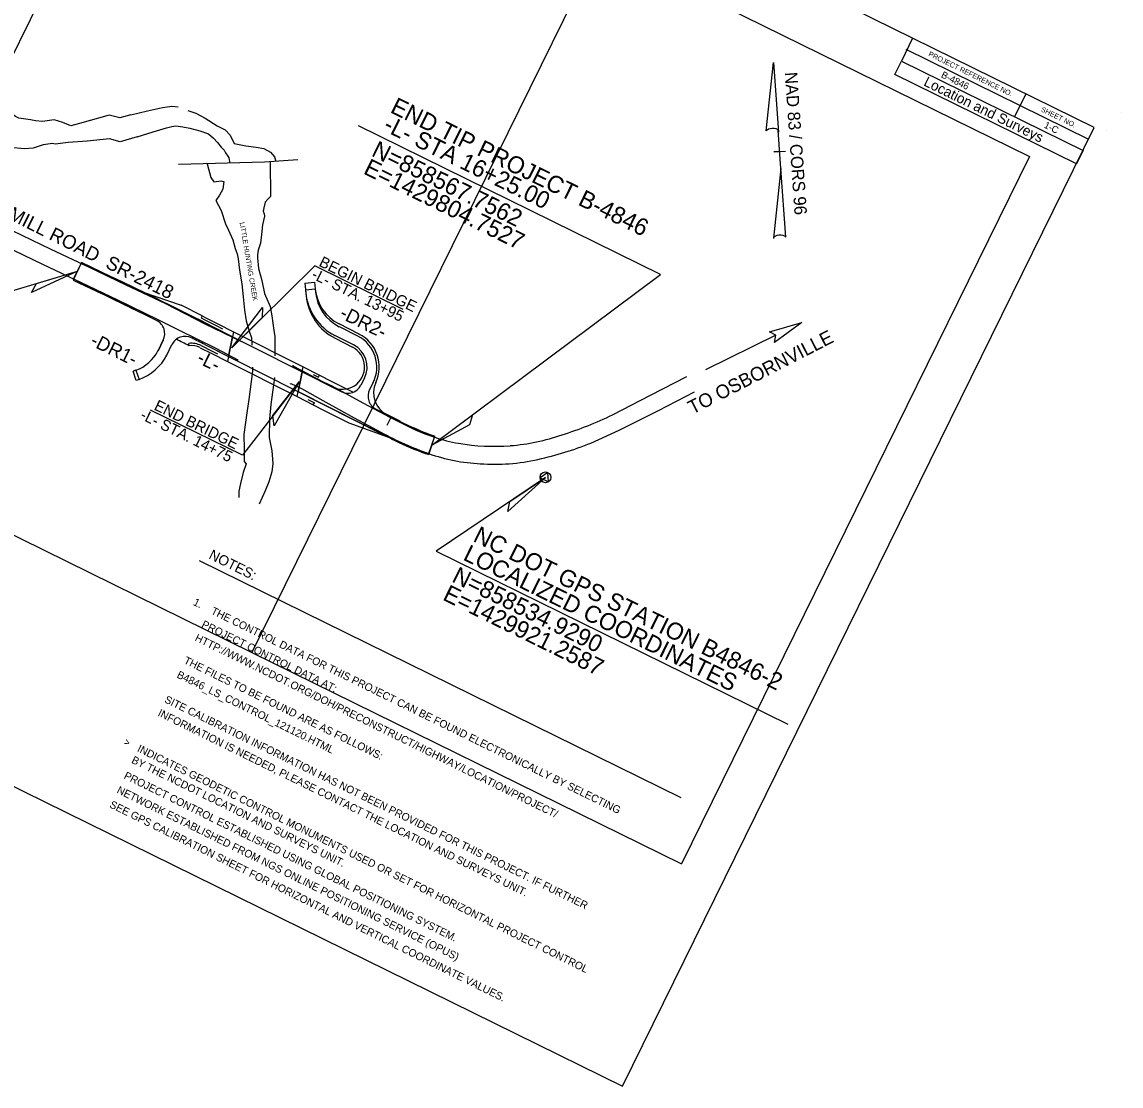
# Model space of a CAD drawing. Extents: x 1428428 to 1430511, y 857911 to 859585.
# Drawn here: x 1429385 to 1430511, y 857911 to 859002 of the extents above; entities that cross this region are included whole.
import ezdxf

# ---------------------------------------------------------------- set-up
doc = ezdxf.new("R2010")
doc.units = 0
for name, color, linetype in [('CTL NGS Horizontal CELL', 7, 'Continuous'), ('CTL Sheet Border CELL', 7, 'Continuous'), ('CTL Sheet Datum Description CELL', 7, 'Continuous'), ('CTL Sheet Notes CELL', 7, 'Continuous'), ('Default', 7, 'Continuous'), ('Exist Hydro Jurisdictional Stream or Body of Water', 7, 'Continuous'), ('Exist Other Culture Dam', 7, 'Continuous'), ('Exist Roads EOP', 7, 'Continuous'), ('Prop Conc Shoulder Berm Gutter', 7, 'Continuous'), ('Prop EOT', 7, 'Continuous'), ('Prop Paved Shoulder', 7, 'Continuous'), ('Prop Roadway Bridge', 7, 'Continuous'), ('Scratch_Level_0', 7, 'Continuous'), ('Scratch_Level_3', 7, 'Continuous'), ('Sheet Data Field CELL', 7, 'Continuous')]:
    doc.layers.add(name, color=color, linetype=linetype)

# ---------------------------------------------------------------- blocks, each defined once
blk = doc.blocks.new('CTL NGS HORIZONTAL')
at = {"layer": 'CTL NGS Horizontal CELL'}
blk.add_line((0, 0), (0, 0), dxfattribs=at)
blk.add_lwpolyline([(-0.064, -0.037), (0.064, -0.037), (0, 0.074), (-0.064, -0.037)], dxfattribs=at)
blk.add_circle((0, 0), 0.0738, dxfattribs=at)

msp = doc.modelspace()

# ---------------------------------------------------------------- linework, layer by layer
at = {"layer": 'CTL Sheet Border CELL'}
for p, q in [((1430297.8, 858985.3), (1430286.3, 858961.8)), ((1430291, 858974.1), (1430478.3, 858881.9)), ((1430413.8, 858928.2), (1430402.3, 858904.8)), ((1430511.5, 858909.2), (1430511.5, 858909.2)), ((1430496.9, 858890.3), (1430496.9, 858890.3)), ((1430496.9, 858890.3), (1430496.9, 858890.3))]:
    msp.add_line(p, q, dxfattribs=at)
for points in [[(1430484, 858893.6), (1429079.6, 859584.7), (1428595.9, 858601.6), (1430000.3, 857910.6)], [(1430286.3, 858961.8), (1430472.5, 858870.2), (1430465.7, 858856.4), (1430279.5, 858948.1)]]:
    msp.add_lwpolyline(points, close=True, dxfattribs=at)
at = {"layer": 'CTL Sheet Notes CELL'}
msp.add_line((1429566.2, 858449.5), (1430060, 858206.5), dxfattribs=at)
at = {"layer": 'Default'}
for p, q in [((1430147.7, 858890.2), (1430155.2, 858960.4)), ((1430155.3, 858960.5), (1430155.2, 858960.4)), ((1430155.3, 858960.5), (1430155.2, 858960.4)), ((1430155.3, 858960.5), (1430160.2, 858888.9)), ((1430162.8, 858851.8), (1430160.1, 858891)), ((1430160.2, 858888.9), (1430160.1, 858890.9)), ((1430155.6, 858868.8), (1430155.5, 858868.7)), ((1430160.9, 858869.1), (1430155.6, 858868.8)), ((1430155.7, 858868.8), (1430167.6, 858869.6)), ((1430162.8, 858851.8), (1430155.2, 858780.2)), ((1430167.7, 858781.4), (1430162.8, 858851.8)), ((1429246.2, 858687.6), (1429441.4, 858746.3)), ((1429599.6, 858667.9), (1429684.9, 858751.7)), ((1429775.5, 858707.1), (1429684.9, 858751.7)), ((1430157.5, 858680.6), (1430085.4, 858645.2)), ((1429668.7, 858633), (1429610.6, 858557.5)), ((1429610.6, 858557.5), (1429516.3, 858603.9))]:
    msp.add_line(p, q, dxfattribs=at)
for points in [[(1429804.7, 858567.8), (1430039.3, 858743.1), (1429729.5, 858895.5)], [(1429921.3, 858534.9), (1429809.1, 858459.2), (1430169.8, 858281.7)]]:
    msp.add_lwpolyline(points, dxfattribs=at)
for points in [[(1429441.4, 858746.3), (1429394.2, 858724.4), (1429399.3, 858733.6)], [(1429599.6, 858667.9), (1429631.1, 858709.2), (1429630.9, 858698.7)], [(1430151.2, 858684), (1430184.1, 858693.6), (1430156.3, 858673.3), (1430157.5, 858680.6)], [(1429668.7, 858633), (1429643.1, 858587.7), (1429641.9, 858598.2)], [(1429804.7, 858567.8), (1429846.4, 858598.9), (1429843.3, 858588.8)], [(1429921.3, 858534.9), (1429882.7, 858500), (1429884.9, 858510.3)]]:
    msp.add_lwpolyline(points, close=True, dxfattribs=at)
for centre, start_param, end_param in [((1430154, 858889.9), 0.216388, 2.908219), ((1430161.5, 858780.4), 0.201328, 3.141593)]:
    msp.add_ellipse(centre, major_axis=(6.33, 0.39), ratio=0.461098, start_param=start_param, end_param=end_param, dxfattribs=at)
at = {"layer": 'Exist Hydro Jurisdictional Stream or Body of Water'}
for points in [[(1429496.1, 858906.8), (1429485, 858903.6), (1429474, 858906.5), (1429443.7, 858898), (1429434.6, 858895.6), (1429426.5, 858899), (1429417.5, 858901.5), (1429405.7, 858899.9), (1429398.5, 858900.6), (1429393.3, 858901.7), (1429381.5, 858903.3), (1429378, 858905.2), (1429372.1, 858909.4), (1429367.1, 858910.6), (1429362.2, 858912.1), (1429362.2, 858912.2)], [(1429496.1, 858906.8), (1429513.2, 858910.8), (1429528.5, 858914.2), (1429538.4, 858915.5), (1429544.7, 858914.9)], [(1429554.8, 858911.3), (1429562.8, 858908.4), (1429572.3, 858903.4), (1429584.8, 858895.6), (1429592.9, 858891.2), (1429598.2, 858885.9), (1429602, 858877.5), (1429614.1, 858874.9), (1429624.8, 858873.5), (1429632.6, 858872.2), (1429639.5, 858868.3), (1429643.4, 858863.7), (1429644.7, 858859.1)], [(1429502.6, 858884.1), (1429485.3, 858879.1), (1429474.2, 858882), (1429451.4, 858879.7), (1429431.8, 858878.5), (1429418.7, 858876.6), (1429415.9, 858877.4), (1429406.2, 858876), (1429396.1, 858872.6), (1429387.1, 858871.9), (1429372.6, 858873.2), (1429361.1, 858876.6), (1429353.7, 858881.2), (1429349.9, 858886.1), (1429346.5, 858892.4), (1429345.9, 858893.4)], [(1429502.6, 858884.1), (1429519.2, 858889.3), (1429532.6, 858893.3), (1429538.2, 858894.8), (1429542.4, 858895.4), (1429549.4, 858894.5), (1429556.6, 858892.9), (1429566.9, 858890.4), (1429575.8, 858887.1), (1429580.8, 858882.7), (1429584.9, 858878.4), (1429588.8, 858873.5), (1429592, 858870.4), (1429592.4, 858869.8), (1429593.4, 858867.6), (1429595.8, 858864.4), (1429596.6, 858862.5), (1429597.6, 858857.2)], [(1429574.5, 858856.6), (1429578.3, 858842.4), (1429581.4, 858838.1), (1429588.9, 858838.9), (1429591.7, 858838.2), (1429590.6, 858830.4), (1429587.1, 858824.3), (1429583.5, 858818.8), (1429588.7, 858808.5), (1429593.3, 858795.1), (1429596.4, 858788.5), (1429600.9, 858778.7), (1429603.1, 858769.6), (1429605.2, 858764.2), (1429606.2, 858759.2), (1429607.7, 858747.4), (1429610.1, 858733.3), (1429611.4, 858719.9), (1429612.8, 858706.5), (1429614.4, 858695.4), (1429617.5, 858684.7), (1429619.9, 858678.1), (1429620.1, 858670.5)], [(1429639.2, 858858.7), (1429639.5, 858823), (1429636.8, 858820.2), (1429633.9, 858817.1), (1429632.5, 858811.5), (1429632.1, 858809.7), (1429631.9, 858808), (1429632.9, 858805.2), (1429633.4, 858802.7), (1429631.3, 858793.8), (1429630.2, 858783.9), (1429629.3, 858775), (1429626.9, 858767.9), (1429625.9, 858763.3), (1429626.2, 858759.9), (1429627, 858749), (1429630.4, 858736.8), (1429633.4, 858723.6), (1429638.9, 858710), (1429640.9, 858700.6), (1429642.8, 858685.6), (1429643.9, 858679.7), (1429644, 858659.7)], [(1429620.8, 858647.8), (1429621, 858643.8), (1429617.3, 858614.6), (1429615.1, 858601.1), (1429612.2, 858579), (1429612.4, 858563), (1429612.5, 858551.3), (1429614.4, 858548.7)], [(1429643.5, 858637.3), (1429639.7, 858609.6), (1429638.4, 858594.8), (1429638.1, 858575.8), (1429640.7, 858562), (1429641.7, 858549), (1429641.7, 858549)], [(1429614.4, 858548.7), (1429611.5, 858540), (1429608.6, 858528.6), (1429606.8, 858520.9), (1429606.8, 858514.1)], [(1429641.7, 858549), (1429640.8, 858540.7), (1429637.8, 858530.3), (1429633.9, 858521.2), (1429627.8, 858507.3)]]:
    msp.add_lwpolyline(points, dxfattribs=at)
at = {"layer": 'Exist Other Culture Dam'}
for points in [[(1429633.4, 858858.3), (1429545, 858855.7)], [(1429667.4, 858860.7), (1429633.4, 858858.3)]]:
    msp.add_lwpolyline(points, dxfattribs=at)
at = {"layer": 'Exist Roads EOP'}
for points in [[(1429247.1, 858849.4), (1429291.1, 858828.3), (1429333.8, 858807.9), (1429374.5, 858788.2), (1429414.2, 858769), (1429453.3, 858750.4), (1429491.1, 858732.4), (1429531.7, 858713.2), (1429572.1, 858692.5), (1429609.6, 858674.3)], [(1429239.4, 858833.7), (1429245.5, 858830.5), (1429265.2, 858821), (1429283.2, 858812.3), (1429325.6, 858792.2), (1429366.8, 858772.3), (1429405.5, 858753.6), (1429445.2, 858734.7), (1429482.4, 858716.9), (1429524, 858696.7), (1429545.9, 858685.8), (1429564, 858677), (1429564, 858677), (1429583.3, 858667.3), (1429605.9, 858655.6), (1429606.4, 858655.4)], [(1429662.7, 858649), (1429662.5, 858650.1)], [(1429678.5, 858640.9), (1429662.7, 858649)], [(1429659.6, 858630.8), (1429660.1, 858631.1), (1429671.1, 858625.9), (1429685.1, 858618.3), (1429693.1, 858613.9), (1429725.3, 858595.8), (1429752.6, 858581.2)], [(1429678.5, 858640.9), (1429693.3, 858632.9), (1429702.2, 858628.7), (1429734.1, 858611.4), (1429761.8, 858596.5), (1429784.3, 858585.4)], [(1429990.1, 858599), (1430029.1, 858619.2), (1430066.2, 858638.3)], [(1429968, 858570.1), (1429997, 858583.2), (1430037.1, 858603.4), (1430074.2, 858622.6)]]:
    msp.add_lwpolyline(points, dxfattribs=at)
for centre, radius, start, end in [((1429829.3, 858929.6), 367.6, 287.2665, 295.9357), ((1429867.6, 858761.7), 195.1, 244.7166, 259.5625), ((1429915, 858879), 339.2, 241.3983, 250.5044), ((1429869, 858776.9), 210.1, 274.4312, 289.2866), ((1429868.6, 858777), 210.3, 260.0502, 274.5337), ((1429830.5, 858917.7), 373.8, 282.8571, 291.5838), ((1429863.1, 858732.4), 183.7, 250.4809, 267.3188), ((1429869.7, 858744.2), 195.9, 265.5537, 282.9501)]:
    msp.add_arc(centre, radius, start, end, dxfattribs=at)
at = {"layer": 'Prop Conc Shoulder Berm Gutter'}
for p, q in [((1429569.4, 858700.5), (1429573.2, 858698.5)), ((1429573.2, 858698.5), (1429584.8, 858692.7)), ((1429584.8, 858692.7), (1429601.5, 858684.2)), ((1429567.3, 858667.9), (1429578.5, 858662.3)), ((1429578.5, 858662.3), (1429595.2, 858653.8)), ((1429672.9, 858648.1), (1429689.7, 858639.7)), ((1429666.6, 858617.7), (1429683.3, 858609.3))]:
    msp.add_line(p, q, dxfattribs=at)
msp.add_arc((1429558.3, 858650.1), 20, 63.1175, 96.715, dxfattribs=at)
at = {"layer": 'Prop EOT'}
for p, q in [((1429437.5, 858738.4), (1429445.2, 858754.3)), ((1429445.2, 858754.3), (1429490.7, 858733.6)), ((1429437.5, 858738.4), (1429482.1, 858715.6)), ((1429674.6, 858734.1), (1429684.5, 858735.1)), ((1429674.6, 858734.1), (1429675.6, 858724)), ((1429684.5, 858735.1), (1429685.6, 858725)), ((1429581, 858689), (1429711.9, 858622.8)), ((1429729.1, 858679.7), (1429710, 858689.4)), ((1429524.1, 858664.8), (1429529.4, 858675.6)), ((1429724.5, 858670.8), (1429705.5, 858680.5)), ((1429533, 858660.4), (1429538.4, 858671.1)), ((1429572, 858671.1), (1429754.5, 858578.9)), ((1429501.4, 858644.8), (1429498.5, 858643.8)), ((1429501.8, 858634.4), (1429498.5, 858643.8)), ((1429504.6, 858635.4), (1429501.8, 858634.4)), ((1429735.7, 858636.6), (1429732.1, 858629.4)), ((1429744.6, 858632.1), (1429741, 858625)), ((1429747.6, 858604.8), (1429763.2, 858597)), ((1429801.9, 858559.2), (1429807.6, 858576.2))]:
    msp.add_line(p, q, dxfattribs=at)
for centre, radius, start, end in [((1426871.4, 853324.5), 6010, 63.20125, 64.16161), ((1429730.3, 858729.5), 55, 185.7616, 243.1111), ((1429730.3, 858729.5), 45, 185.7616, 243.1111), ((1426871.4, 853324.5), 5990, 63.7291, 64.16106), ((1429516, 858682.3), 15, 333.6387, 63.7291), ((1429551.8, 858664.5), 15, 63.3455, 153.6387), ((1426871.4, 853324.5), 5990, 63.20125, 63.34553), ((1429713, 858648.1), 35.4, 333.1111, 63.1111), ((1429488.2, 858682.6), 40, 289.1404, 333.6387), ((1429713, 858648.1), 25.4, 333.1111, 63.1111), ((1429488.2, 858682.6), 50, 289.1404, 333.6387), ((1429718.7, 858636.2), 15, 243.2012, 333.1111), ((1429754.4, 858618.2), 15, 153.1111, 243.2012), ((1429917.2, 858867.9), 311.6, 240.386, 249.4058), ((1429943, 858964.6), 429.3, 243.9614, 250.8147)]:
    msp.add_arc(centre, radius, start, end, dxfattribs=at)
at = {"layer": 'Prop Paved Shoulder'}
for p, q in [((1429508.8, 858724.8), (1429547.8, 858711.4)), ((1429569.4, 858700.5), (1429547.8, 858711.4)), ((1429569.4, 858700.5), (1429568.3, 858698.4)), ((1429568.3, 858698.4), (1429572.1, 858696.5)), ((1429572.2, 858696.5), (1429583.8, 858690.6)), ((1429583.8, 858690.6), (1429590.3, 858687.3)), ((1429555.9, 858669.9), (1429555.6, 858672.3)), ((1429568.4, 858670), (1429579.5, 858664.4)), ((1429579.5, 858664.4), (1429585, 858661.6)), ((1429683.2, 858640.3), (1429688.6, 858637.6)), ((1429688.6, 858637.6), (1429689.7, 858639.7)), ((1429689.7, 858639.7), (1429700.8, 858634)), ((1429700.9, 858634), (1429724.1, 858622.2)), ((1429677.8, 858614.7), (1429684.4, 858611.3)), ((1429683.3, 858609.3), (1429684.4, 858611.3)), ((1429683.3, 858609.3), (1429694.5, 858603.6)), ((1429694.5, 858603.6), (1429719.8, 858590.7)), ((1429719.8, 858590.7), (1429759.4, 858576.6))]:
    msp.add_line(p, q, dxfattribs=at)
for centre, radius, start, end in [((1426871.4, 853324.5), 5981.7, 63.33384, 63.47406), ((1429558.3, 858650.1), 22.3, 63.1231, 96.715)]:
    msp.add_arc(centre, radius, start, end, dxfattribs=at)
at = {"layer": 'Prop Roadway Bridge'}
for p, q in [((1429601.5, 858684.2), (1429595.2, 858653.8)), ((1429601.5, 858684.2), (1429672.9, 858648.1)), ((1429595.2, 858653.8), (1429666.6, 858617.7)), ((1429666.6, 858617.7), (1429672.9, 858648.1))]:
    msp.add_line(p, q, dxfattribs=at)
at = {"layer": 'Scratch_Level_0'}
msp.add_line((1429763.2, 858596.9), (1429758.6, 858588), dxfattribs=at)
at = {"layer": 'Scratch_Level_3'}
for p, q in [((1429537, 859297.3), (1429180, 858572)), ((1429977.4, 859080.6), (1429620.4, 858355.3)), ((1429977.4, 859080.6), (1430417.8, 858863.9)), ((1430417.8, 858863.9), (1430060.8, 858138.6)), ((1429180, 858572), (1429620.4, 858355.3)), ((1429620.4, 858355.3), (1430060.8, 858138.6))]:
    msp.add_line(p, q, dxfattribs=at)
at = {"layer": 'Sheet Data Field CELL'}
for p, q in [((1429445.7, 858755.3), (1429437, 858737.3)), ((1429475.4, 858741), (1429445.7, 858755.3)), ((1429437, 858737.3), (1429466.7, 858723)), ((1429685.3, 858728), (1429675.3, 858726.9)), ((1429675.3, 858726.9), (1429675.9, 858721)), ((1429600.5, 858679.1), (1429581, 858689)), ((1429730.2, 858681.9), (1429709.7, 858692.3)), ((1429529.4, 858675.6), (1429524.1, 858664.8)), ((1429596.2, 858658.9), (1429600.5, 858679.1)), ((1429705.8, 858677.5), (1429723.4, 858668.6)), ((1429533, 858660.4), (1429538.4, 858671.1)), ((1429572, 858671.1), (1429596.2, 858658.9)), ((1429501.4, 858644.8), (1429504.6, 858635.4)), ((1429671.9, 858643.1), (1429667.6, 858622.8)), ((1429702.5, 858627.8), (1429671.9, 858643.1)), ((1429667.6, 858622.8), (1429763.2, 858574.6)), ((1429772.2, 858592.4), (1429758.8, 858599.2)), ((1429801.6, 858558.3), (1429807.9, 858577.2))]:
    msp.add_line(p, q, dxfattribs=at)
for centre, radius, start, end in [((1426871.4, 853324.5), 6010, 63.20125, 64.32444), ((1426871.4, 853324.5), 5990, 63.7291, 64.32444), ((1429730.6, 858726.6), 55, 185.7616, 243.1111), ((1429730, 858732.5), 45, 185.7616, 243.1111), ((1429516, 858682.3), 15, 333.6387, 63.7291), ((1429551.8, 858664.5), 15, 63.3455, 153.6387), ((1426871.4, 853324.5), 5990, 63.20125, 63.34553), ((1429713, 858648.1), 37.9, 334.9977, 63.1111), ((1429488.2, 858682.6), 40, 289.1404, 333.6387), ((1429713, 858648.1), 22.9, 242.5322, 63.1111), ((1429488.2, 858682.6), 50, 289.1404, 333.6387), ((1429770.1, 858621.5), 25, 154.9977, 243.1111), ((1429903.4, 858851), 290, 243.1111, 249.4211), ((1429903.4, 858851), 310, 243.1111, 249.4202), ((1429868.2, 858757.4), 190, 249.4214, 251.5016), ((1429868.2, 858757.4), 210, 249.4199, 251.5016)]:
    msp.add_arc(centre, radius, start, end, dxfattribs=at)

# ---------------------------------------------------------------- block references
at = {"layer": 'CTL NGS Horizontal CELL', "xscale": 74.99999999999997, "yscale": 74.99999999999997, "rotation": -24.963754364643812}
msp.add_blockref('CTL NGS HORIZONTAL', (1429921.3, 858534.9), dxfattribs=at)

# ---------------------------------------------------------------- texts
at = {"layer": 'CTL Sheet Border CELL'}
for s, height, p in [('PROJECT REFERENCE NO.', 5.217, (1430313.5, 858967.4)), ('Location and Surveys', 10.435, (1430308.3, 858937.2)), ('SHEET NO.', 5.22, (1430428.8, 858910.6))]:
    msp.add_text(s, height=height, rotation=333.8001, dxfattribs=at).set_placement(p)
at = {"layer": 'CTL Sheet Datum Description CELL'}
for s, p in [('B-4846', (1430326.4, 858945.5)), ('1-C', (1430431.8, 858893.9))]:
    msp.add_text(s, height=7, rotation=333.8001, dxfattribs=at).set_placement(p)
at = {"layer": 'CTL Sheet Notes CELL'}
for s, height, rotation, p in [('NOTES:', 10.43, 333.6949, (1429575.3, 858452)), ('1.    THE CONTROL DATA FOR THIS PROJECT CAN BE FOUND ELECTRONICALLY BY SELECTING', 7.826, 333.8001, (1429559.4, 858404.3)), ('PROJECT CONTROL DATA AT:', 7.826, 333.8001, (1429568, 858381.6)), ('HTTP://WWW.NCDOT.ORG/DOH/PRECONSTRUCT/HIGHWAY/LOCATION/PROJECT/', 7.826, 333.8001, (1429561.2, 858367.7)), ('THE FILES TO BE FOUND ARE AS FOLLOWS:', 7.826, 333.8001, (1429549.8, 858344.5)), ('B4846_LS_CONTROL_121120.HTML', 7.826, 333.8001, (1429542.6, 858329.9)), ('SITE CALIBRATION INFORMATION HAS NOT BEEN PROVIDED FOR THIS PROJECT. IF FURTHER', 7.826, 333.8001, (1429530, 858304.4)), ('INFORMATION IS NEEDED, PLEASE CONTACT THE LOCATION AND SURVEYS UNIT.', 7.826, 333.8001, (1429523.2, 858290.6)), ('>', 7.34, 333.6948, (1429488.2, 858261.1)), ('INDICATES GEODETIC CONTROL MONUMENTS USED OR SET FOR HORIZONTAL PROJECT CONTROL', 7.826, 333.6949, (1429502, 858254.1)), ('BY THE NCDOT LOCATION AND SURVEYS UNIT.', 7.826, 333.6949, (1429496.2, 858242.4)), ('PROJECT CONTROL ESTABLISHED USING GLOBAL POSITIONING SYSTEM.', 7.826, 333.6949, (1429488.4, 858226.4)), ('NETWORK ESTABLISHED FROM NGS ONLINE POSITIONING SERVICE (OPUS)', 7.826, 333.6949, (1429481.1, 858211.6)), ('SEE GPS CALIBRATION SHEET FOR HORIZONTAL AND VERTICAL COORDINATE VALUES.', 7.826, 333.6949, (1429473.7, 858196.7))]:
    msp.add_text(s, height=height, rotation=rotation, dxfattribs=at).set_placement(p)
at = {"layer": 'Default'}
for s, height, rotation, p in [('NAD 83 / CORS 96', 12.75, 273.9476, (1430166.7, 858950.2)), ('MITCHELL MILL ROAD  SR-2418', 14.062, 333.3655, (1429281.5, 858844.6)), ('LITTLE HUNTING CREEK', 5, 279.6903, (1429607.7, 858796.2)), ('BEGIN BRIDGE', 11.25, 333.8001, (1429688.2, 858752.1)), ('-L- STA. 13+95 ', 11.25, 333.8001, (1429680.6, 858739.4)), ('-DR2-', 14.06, 333.8001, (1429709.3, 858699)), ('-DR1-', 14.06, 333.8001, (1429453.6, 858670.9)), ('TO OSBORNVILLE', 14.063, 27.1845, (1430072, 858599.2)), ('-L-', 14.06, 333.8001, (1429562.9, 858653.1)), ('END BRIDGE', 11.25, 333.8001, (1429519.1, 858604.8)), ('-L- STA. 14+75', 11.25, 333.8001, (1429505, 858595.3))]:
    msp.add_text(s, height=height, rotation=rotation, dxfattribs=at).set_placement(p)
at = {"layer": 'Sheet Data Field CELL'}
for s, p in [('END TIP PROJECT B-4846', (1429761.2, 858909.6)), ('-L- STA 16+25.00', (1429754, 858891.2)), ('N=858567.7562', (1429741.9, 858865.1)), ('E=1429804.7527', (1429733.6, 858846.8)), ('NC DOT GPS STATION B4846-2', (1429846.1, 858469.8)), ('LOCALIZED COORDINATES', (1429835.8, 858450.8)), ('N=858534.9290', (1429824.3, 858428.3)), ('E=1429921.2587', (1429814.9, 858409.7))]:
    msp.add_text(s, height=17.5, rotation=333.8001, dxfattribs=at).set_placement(p)

doc.saveas('drawing.dxf')
